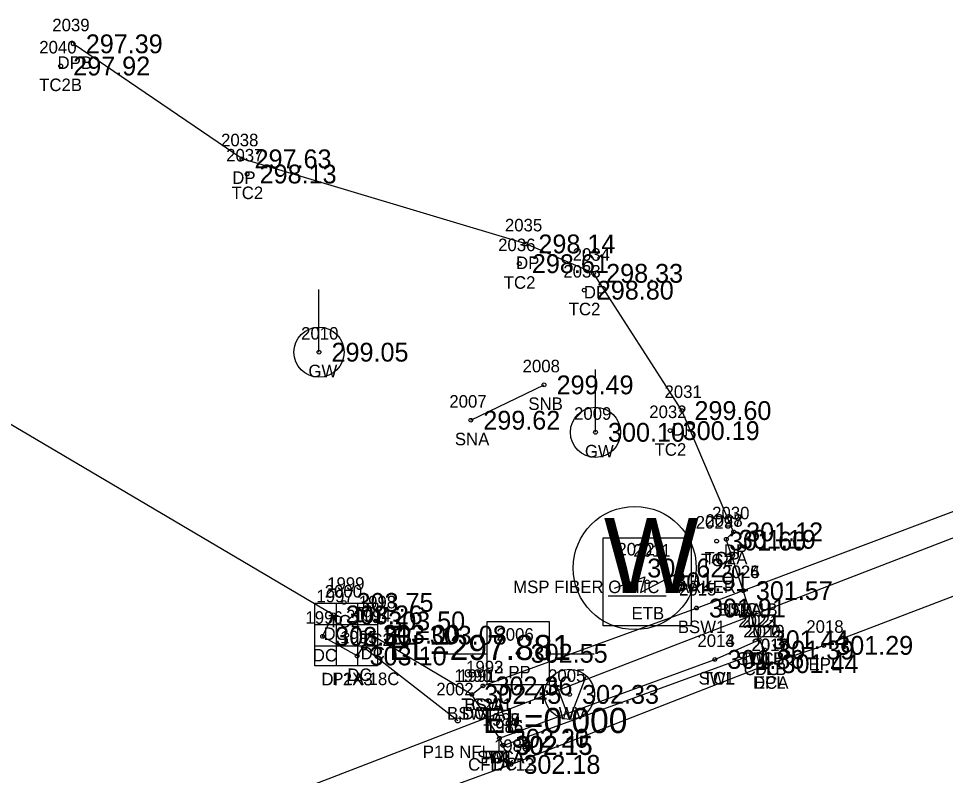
# Model space of a CAD drawing. Extents: x 1970076 to 1971136, y 803126 to 804215.
# Drawn here: x 1970746.3 to 1970820.2, y 803676.7 to 803737 of the extents above; entities that cross this region are included whole.
import ezdxf

# ---------------------------------------------------------------- set-up
doc = ezdxf.new("R2010")
doc.units = 0
for name, color, linetype in [('RD_EX_BldgApp', 7, 'Continuous'), ('RD_EX_BldgApp_txCode', 7, 'Continuous'), ('RD_EX_Conc', 7, 'Continuous'), ('RD_EX_Conc_txCode', 7, 'Continuous'), ('RD_EX_DR_Inlet', 7, 'Continuous'), ('RD_EX_DR_Inlet_txCode', 7, 'Continuous'), ('RD_EX_DR_Pipe', 7, 'Continuous'), ('RD_EX_DR_Pipe_txCode', 7, 'Continuous'), ('RD_EX_Driveway', 7, 'Continuous'), ('RD_EX_Driveway_txCode', 7, 'Continuous'), ('RD_EX_Misc_txCode', 7, 'Continuous'), ('RD_EX_Road', 7, 'Continuous'), ('RD_EX_Road_txCode', 7, 'Continuous'), ('RD_EX_TX_BldgApp_ELEV', 7, 'Continuous'), ('RD_EX_TX_Conc_ELEV', 7, 'Continuous'), ('RD_EX_TX_DR_Inlet_ELEV', 7, 'Continuous'), ('RD_EX_TX_Driveway_ELEV', 7, 'Continuous'), ('RD_EX_TX_Misc_ELEV', 7, 'Continuous'), ('RD_EX_TX_Road_ELEV', 7, 'Continuous'), ('RD_EX_TX_UT_ELEV', 7, 'Continuous'), ('RD_EX_UT', 7, 'Continuous'), ('RD_EX_UT_txCode', 7, 'Continuous'), ('RD_HC_Survey_ELEV', 7, 'Continuous'), ('RD_SMD_Locator', 7, 'Continuous'), ('RD_TX_Pipe_ElevEX', 7, 'Continuous')]:
    doc.layers.add(name, color=color, linetype=linetype)

msp = doc.modelspace()

# ---------------------------------------------------------------- linework, layer by layer
at = {"layer": 'RD_EX_BldgApp'}
msp.add_line((1970782.377, 803705.016), (1970788.22, 803707.832), dxfattribs=at)
at = {"layer": 'RD_EX_Conc'}
msp.add_line((1970784.957, 803679.091), (1970805.813, 803686.703), dxfattribs=at)
for points in [[(1970785.576, 803677.586), (1970784.923, 803679.121), (1970784.66, 803679.671), (1970782.456, 803683.164), (1970774.374, 803687.953), (1970773.313, 803686.231), (1970770.566, 803687.793), (1970771.418, 803689.504), (1970717.98, 803721.005)], [(1970806.155, 803685.614), (1970805.813, 803686.703), (1970805.374, 803687.523), (1970804.106, 803691.434), (1970830.051, 803701.222), (1970831.15, 803697.041), (1970831.56, 803696.461), (1970832.409, 803695.41)], [(1970782.456, 803683.164), (1970783.35, 803683.843), (1970800.368, 803690.048), (1970804.106, 803691.434)], [(1970784.66, 803679.671), (1970801.832, 803685.954), (1970805.374, 803687.523)]]:
    msp.add_lwpolyline(points, dxfattribs=at)
at = {"layer": 'RD_EX_DR_Inlet'}
for p, q in [((1970771.646, 803690.444), (1970771.646, 803685.444)), ((1970773.346, 803690.444), (1970773.346, 803685.444)), ((1970769.946, 803688.744), (1970774.946, 803688.744)), ((1970769.946, 803687.044), (1970774.946, 803687.044))]:
    msp.add_line(p, q, dxfattribs=at)
msp.add_lwpolyline([(1970769.946, 803685.444), (1970769.946, 803690.444), (1970774.946, 803690.444), (1970774.946, 803685.444)], close=True, dxfattribs=at)
at = {"layer": 'RD_EX_DR_Pipe'}
for p, q in [((1970722.35, 803657.704), (1970845.026, 803704.964)), ((1970773.868, 803686.907), (1970781.34, 803681.089))]:
    msp.add_line(p, q, dxfattribs=at)
at = {"layer": 'RD_EX_Driveway'}
msp.add_lwpolyline([(1970804.106, 803691.434), (1970802.751, 803695.525), (1970803.332, 803696.117), (1970799.209, 803705.786), (1970792.17, 803716.722), (1970786.77, 803719.063), (1970764.14, 803725.844), (1970750.683, 803735.009)], dxfattribs=at)
at = {"layer": 'RD_EX_Road'}
msp.add_lwpolyline([(1970591.954, 803626.632), (1970595.635, 803624.223), (1970603.942, 803620.228), (1970610.887, 803618.117), (1970618.557, 803616.952), (1970618.557, 803616.952), (1970625.287, 803616.418), (1970639.009, 803619.104), (1970654.348, 803624.92), (1970666.821, 803630.043), (1970700.041, 803645.213), (1970717.462, 803652.2), (1970737.462, 803660.017), (1970785.576, 803677.586), (1970806.155, 803685.614), (1970810.513, 803687.074), (1970832.409, 803695.41), (1970845.906, 803700.393), (1970902.879, 803721.466)], dxfattribs=at)
at = {"layer": 'RD_EX_UT'}
for p, q in [((1970770.277, 803710.438), (1970770.277, 803715.438)), ((1970792.32, 803704.051), (1970792.32, 803709.051)), ((1970793.323, 803691.029), (1970797.952, 803691.029)), ((1970788.646, 803688.952), (1970783.646, 803688.952)), ((1970783.646, 803688.952), (1970783.646, 803683.952)), ((1970788.646, 803683.952), (1970788.646, 803688.952)), ((1970780.215, 803686.389), (1970783.684, 803686.389)), ((1970788.574, 803686.389), (1970792.215, 803686.389)), ((1970790.249, 803681.174), (1970788.946, 803684.656)), ((1970790.249, 803681.174), (1970791.571, 803684.619)), ((1970783.646, 803683.952), (1970788.646, 803683.952))]:
    msp.add_line(p, q, dxfattribs=at)
msp.add_lwpolyline([(1970792.939, 803688.641), (1970792.939, 803695.641), (1970799.939, 803695.641), (1970799.939, 803688.641)], close=True, dxfattribs=at)
msp.add_lwpolyline([(1970793.837, 803691.635), (1970796.26, 803692.535), (1970795.914, 803691.289), (1970798.959, 803692.882)], dxfattribs=at)
for centre, radius in [((1970770.277, 803710.438), 1.999), ((1970792.32, 803704.051), 1.999), ((1970795.451, 803693.237), 4.908), ((1970790.249, 803683.166), 2)]:
    msp.add_circle(centre, radius, dxfattribs=at)
at = {"layer": 'RD_SMD_Locator'}
for centre, radius in [((1970750.683, 803735.009), 0.15), ((1970749.683, 803733.241), 0.15), ((1970764.14, 803725.844), 0.15), ((1970764.545, 803724.635), 0.15), ((1970786.77, 803719.063), 0.15), ((1970786.25, 803717.489), 0.15), ((1970792.17, 803716.722), 0.15), ((1970791.426, 803715.378), 0.15), ((1970770.277, 803710.438), 0.15), ((1970788.22, 803707.832), 0.15), ((1970799.209, 803705.786), 0.15), ((1970782.377, 803705.016), 0.15), ((1970792.32, 803704.051), 0.15), ((1970798.276, 803704.185), 0.15), ((1970803.332, 803696.117), 0.15), ((1970801.979, 803695.383), 0.15), ((1970802.751, 803695.525), 0.15), ((1970802.751, 803695.525), 0.15), ((1970796.439, 803692.141), 0.15), ((1970804.106, 803691.434), 0.15), ((1970804.106, 803691.434), 0.15), ((1970804.106, 803691.434), 0.15), ((1970772.273, 803690.498), 0.15), ((1970800.368, 803690.048), 0.15), ((1970771.418, 803689.504), 0.15), ((1970774.795, 803689.023), 0.15), ((1970770.566, 803687.793), 0.15), ((1970772.484, 803687.886), 0.15), ((1970774.374, 803687.953), 0.15), ((1970805.374, 803687.523), 0.15), ((1970805.374, 803687.523), 0.15), ((1970805.374, 803687.523), 0.15), ((1970810.513, 803687.074), 0.15), ((1970773.868, 803686.907), 0.2), ((1970786.155, 803686.443), 0.15), ((1970805.813, 803686.703), 0.15), ((1970805.813, 803686.703), 0.15), ((1970773.313, 803686.231), 0.15), ((1970801.832, 803685.954), 0.15), ((1970801.832, 803685.954), 0.15), ((1970806.155, 803685.614), 0.15), ((1970806.155, 803685.614), 0.15), ((1970783.35, 803683.843), 0.15), ((1970783.35, 803683.843), 0.15), ((1970782.456, 803683.164), 0.15), ((1970782.456, 803683.164), 0.15), ((1970790.249, 803683.167), 0.15), ((1970781.34, 803681.089), 0.2), ((1970784.66, 803679.671), 0.15), ((1970784.66, 803679.671), 0.15), ((1970784.66, 803679.671), 0.15), ((1970784.923, 803679.121), 0.15), ((1970784.957, 803679.091), 0.15), ((1970785.576, 803677.586), 0.15), ((1970785.576, 803677.586), 0.15)]:
    msp.add_circle(centre, radius, dxfattribs=at)

# ---------------------------------------------------------------- texts
at = {"layer": 'RD_EX_BldgApp_txCode'}
for s, p in [('2008', (1970786.511, 803708.832)), ('2007', (1970780.668, 803706.016)), ('SNB', (1970786.968, 803705.832)), ('SNA', (1970781.109, 803703.016))]:
    msp.add_text(s, height=1, dxfattribs=at).set_placement(p)
at = {"layer": 'RD_EX_Conc_txCode'}
for s, p in [('2040', (1970747.974, 803734.241)), ('TC2B', (1970747.966, 803731.241)), ('2037', (1970762.876, 803725.635)), ('TC2', (1970763.301, 803722.635)), ('2036', (1970784.557, 803718.489)), ('2033', (1970789.757, 803716.378)), ('TC2', (1970785.006, 803715.489)), ('TC2', (1970790.182, 803713.378)), ('2032', (1970796.607, 803705.185)), ('TC2', (1970797.032, 803702.185)), ('2028', (1970801.082, 803696.525)), ('2029', (1970800.309, 803696.383)), ('TC2A', (1970801.019, 803693.525)), ('TC2', (1970800.735, 803693.383)), ('2024', (1970802.436, 803692.434)), ('2025', (1970802.436, 803692.434)), ('1999', (1970770.927, 803691.498)), ('2015', (1970798.982, 803691.048)), ('1997', (1970770.071, 803690.504)), ('1998', (1970773.449, 803690.023)), ('BSW1B', (1970802.153, 803689.434)), ('DC', (1970803.326, 803689.434)), ('1996', (1970769.196, 803688.793)), ('TC2', (1970771.029, 803688.498)), ('1994', (1970773.028, 803688.953)), ('2022', (1970803.705, 803688.523)), ('2023', (1970803.705, 803688.523)), ('2021', (1970803.989, 803688.523)), ('BSW1', (1970798.887, 803688.048)), ('2020', (1970804.105, 803687.703)), ('2019', (1970804.428, 803687.703)), ('DC', (1970770.638, 803687.504)), ('1995', (1970771.967, 803687.231)), ('TC2', (1970773.551, 803687.023)), ('2013', (1970800.446, 803686.954)), ('2014', (1970800.446, 803686.954)), ('2017', (1970804.769, 803686.614)), ('DC', (1970769.786, 803685.793)), ('DC', (1970773.595, 803685.953)), ('SWLB', (1970803.611, 803685.523)), ('TC1B', (1970803.941, 803685.523)), ('DC', (1970804.595, 803685.523)), ('1992', (1970782.004, 803684.843)), ('1993', (1970782.004, 803684.843)), ('CFLB', (1970804.136, 803684.703)), ('DC', (1970805.034, 803684.703)), ('DC', (1970772.534, 803684.231)), ('1990', (1970781.07, 803684.164)), ('1991', (1970781.393, 803684.164)), ('SWL', (1970800.541, 803683.954)), ('TC1', (1970800.871, 803683.954)), ('DCA', (1970804.887, 803683.614)), ('TC2A', (1970781.618, 803681.843)), ('BSW1', (1970781.87, 803681.843)), ('BSW1A', (1970780.487, 803681.164)), ('DC', (1970781.676, 803681.164)), ('1987', (1970783.314, 803680.671)), ('1988', (1970783.314, 803680.671)), ('1989', (1970783.314, 803680.671)), ('1985', (1970783.576, 803680.121)), ('1986', (1970783.587, 803680.091)), ('1984', (1970784.23, 803678.586)), ('SWLA', (1970782.881, 803677.671)), ('TC1A', (1970783.211, 803677.671)), ('DC', (1970783.881, 803677.671)), ('CFLA 12', (1970782.162, 803677.091)), ('DC', (1970784.143, 803677.121))]:
    msp.add_text(s, height=1, dxfattribs=at).set_placement(p)
at = {"layer": 'RD_EX_DR_Inlet_txCode'}
for s, p in [('2000', (1970770.736, 803690.886)), ('DI 2X3', (1970770.468, 803683.886))]:
    msp.add_text(s, height=1, dxfattribs=at).set_placement(p)
at = {"layer": 'RD_EX_DR_Pipe_txCode'}
for s, p in [('2001', (1970772.443, 803688.907)), ('P1A 18C', (1970771.333, 803683.907)), ('2002', (1970779.631, 803683.089)), ('P1B NFL', (1970778.552, 803678.089))]:
    msp.add_text(s, height=1, dxfattribs=at).set_placement(p)
at = {"layer": 'RD_EX_Driveway_txCode'}
for s, p in [('2039', (1970749.014, 803736.009)), ('DPB', (1970749.431, 803733.009)), ('2038', (1970762.47, 803726.844)), ('DP', (1970763.36, 803723.844)), ('2035', (1970785.1, 803720.063)), ('2034', (1970790.501, 803717.722)), ('DP', (1970785.99, 803717.063)), ('DP', (1970791.391, 803714.722)), ('2031', (1970797.823, 803706.786)), ('DP', (1970798.429, 803703.786)), ('2027', (1970801.082, 803696.525)), ('2030', (1970801.623, 803697.117)), ('DP', (1970802.552, 803694.117)), ('DP', (1970801.971, 803693.525)), ('2026', (1970802.413, 803692.434)), ('DPA', (1970802.838, 803689.434))]:
    msp.add_text(s, height=1, dxfattribs=at).set_placement(p)
at = {"layer": 'RD_EX_Misc_txCode'}
for s, p in [('2012', (1970794.065, 803694.237)), ('MSP FIBER OPTIC MARKER', (1970785.758, 803691.237))]:
    msp.add_text(s, height=1, dxfattribs=at).set_placement(p)
at = {"layer": 'RD_EX_Road_txCode'}
for s, p in [('2018', (1970809.127, 803688.074)), ('2016', (1970804.746, 803686.614)), ('EPL', (1970809.308, 803685.074)), ('EPL', (1970804.95, 803683.614)), ('1983', (1970784.23, 803678.586))]:
    msp.add_text(s, height=1, dxfattribs=at).set_placement(p)
at = {"layer": 'RD_EX_TX_BldgApp_ELEV'}
for s, p in [('299.49', (1970789.22, 803707.082)), ('299.62', (1970783.377, 803704.266))]:
    msp.add_text(s, height=1.5, dxfattribs=at).set_placement(p)
at = {"layer": 'RD_EX_TX_Conc_ELEV'}
for s, p in [('297.92', (1970750.683, 803732.491)), ('298.13', (1970765.545, 803723.885)), ('298.61', (1970787.25, 803716.739)), ('298.80', (1970792.426, 803714.628)), ('300.19', (1970799.276, 803703.435)), ('301.60', (1970802.979, 803694.633)), ('301.19', (1970803.751, 803694.775)), ('301.57', (1970805.106, 803690.684)), ('301.57', (1970805.106, 803690.684)), ('303.75', (1970773.273, 803689.748)), ('303.26', (1970772.418, 803688.754)), ('301.91', (1970801.368, 803689.298)), ('303.50', (1970775.795, 803688.273)), ('303.00', (1970775.374, 803687.203)), ('303.33', (1970771.566, 803687.043)), ('301.44', (1970806.374, 803686.773)), ('301.44', (1970806.374, 803686.773)), ('301.44', (1970806.374, 803686.773)), ('301.39', (1970806.813, 803685.953)), ('301.39', (1970806.813, 803685.953)), ('303.10', (1970774.313, 803685.481)), ('301.86', (1970802.832, 803685.204)), ('301.86', (1970802.832, 803685.204)), ('301.44', (1970807.155, 803684.864)), ('302.36', (1970784.35, 803683.093)), ('302.36', (1970784.35, 803683.093)), ('302.45', (1970783.456, 803682.414)), ('302.45', (1970783.456, 803682.414)), ('302.20', (1970785.66, 803678.921)), ('302.20', (1970785.66, 803678.921)), ('302.20', (1970785.66, 803678.921)), ('302.15', (1970785.923, 803678.371)), ('302.15', (1970785.957, 803678.341)), ('302.18', (1970786.576, 803676.836))]:
    msp.add_text(s, height=1.5, dxfattribs=at).set_placement(p)
at = {"layer": 'RD_EX_TX_DR_Inlet_ELEV'}
msp.add_text('EL=303.08', height=1.5, dxfattribs=at).set_placement((1970775.484, 803687.136))
at = {"layer": 'RD_EX_TX_Driveway_ELEV'}
for s, p in [('297.39', (1970751.683, 803734.259)), ('297.63', (1970765.14, 803725.094)), ('298.14', (1970787.77, 803718.313)), ('298.33', (1970793.17, 803715.972)), ('299.60', (1970800.209, 803705.036)), ('301.12', (1970804.332, 803695.367)), ('301.19', (1970803.751, 803694.775)), ('301.57', (1970805.106, 803690.684))]:
    msp.add_text(s, height=1.5, dxfattribs=at).set_placement(p)
at = {"layer": 'RD_EX_TX_Misc_ELEV'}
msp.add_text('301.62', height=1.5, dxfattribs=at).set_placement((1970796.451, 803692.487))
at = {"layer": 'RD_EX_TX_Road_ELEV'}
for s, p in [('301.29', (1970811.513, 803686.324)), ('301.44', (1970807.155, 803684.864)), ('302.18', (1970786.576, 803676.836))]:
    msp.add_text(s, height=1.5, dxfattribs=at).set_placement(p)
at = {"layer": 'RD_EX_TX_UT_ELEV'}
for s, p in [('299.05', (1970771.277, 803709.688)), ('300.10', (1970793.32, 803703.301)), ('301.91', (1970798.439, 803691.391)), ('302.33', (1970791.249, 803682.417))]:
    msp.add_text(s, height=1.5, dxfattribs=at).set_placement(p)
at = {"layer": 'RD_EX_UT'}
msp.add_text('W', height=6, dxfattribs=at).set_placement((1970792.986, 803691.236))
at = {"layer": 'RD_EX_UT_txCode'}
for s, p in [('2010', (1970768.852, 803711.438)), ('GW', (1970769.434, 803708.438)), ('2009', (1970790.612, 803705.051)), ('GW', (1970791.478, 803702.051)), ('2011', (1970795.337, 803694.141)), ('ETB', (1970795.195, 803689.141)), ('2006', (1970784.423, 803687.443)), ('PP', (1970785.375, 803684.443)), ('2005', (1970788.541, 803684.167)), ('WV', (1970789.391, 803681.167))]:
    msp.add_text(s, height=1, dxfattribs=at).set_placement(p)
at = {"layer": 'RD_HC_Survey_ELEV'}
msp.add_text('302.55', height=1.5, dxfattribs=at).set_placement((1970787.155, 803685.693))
at = {"layer": 'RD_TX_Pipe_ElevEX'}
for s, p in [('EL=297.881', (1970775.868, 803685.907)), ('EL=0.000', (1970783.34, 803680.089))]:
    msp.add_text(s, height=2, dxfattribs=at).set_placement(p)

doc.saveas('drawing.dxf')
